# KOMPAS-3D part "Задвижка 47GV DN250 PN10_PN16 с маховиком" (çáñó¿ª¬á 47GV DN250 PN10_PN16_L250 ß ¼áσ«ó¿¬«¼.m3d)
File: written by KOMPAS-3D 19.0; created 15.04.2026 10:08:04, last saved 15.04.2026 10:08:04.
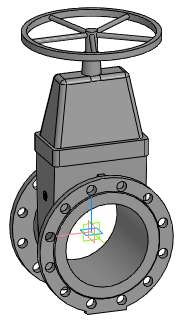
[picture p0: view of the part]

Document properties: Автор: Евгений; Полное имя файла: Z:\3.Личные\kachalov\3d для проектировщиков\2.1 Тип 47GV, 47GV.Z\Задвижка 47GV_DN40-DN600\stp_Задвижка 47GV\Задвижка 47GV DN250 PN10_PN16_L250 с маховиком.m3d

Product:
- Part/product: Задвижка 47GV DN250 PN10_PN16 с маховиком

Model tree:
1. Операция без истории:1  (labels: Задвижка 47GV DN250 PN10_PN16 с маховиком)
